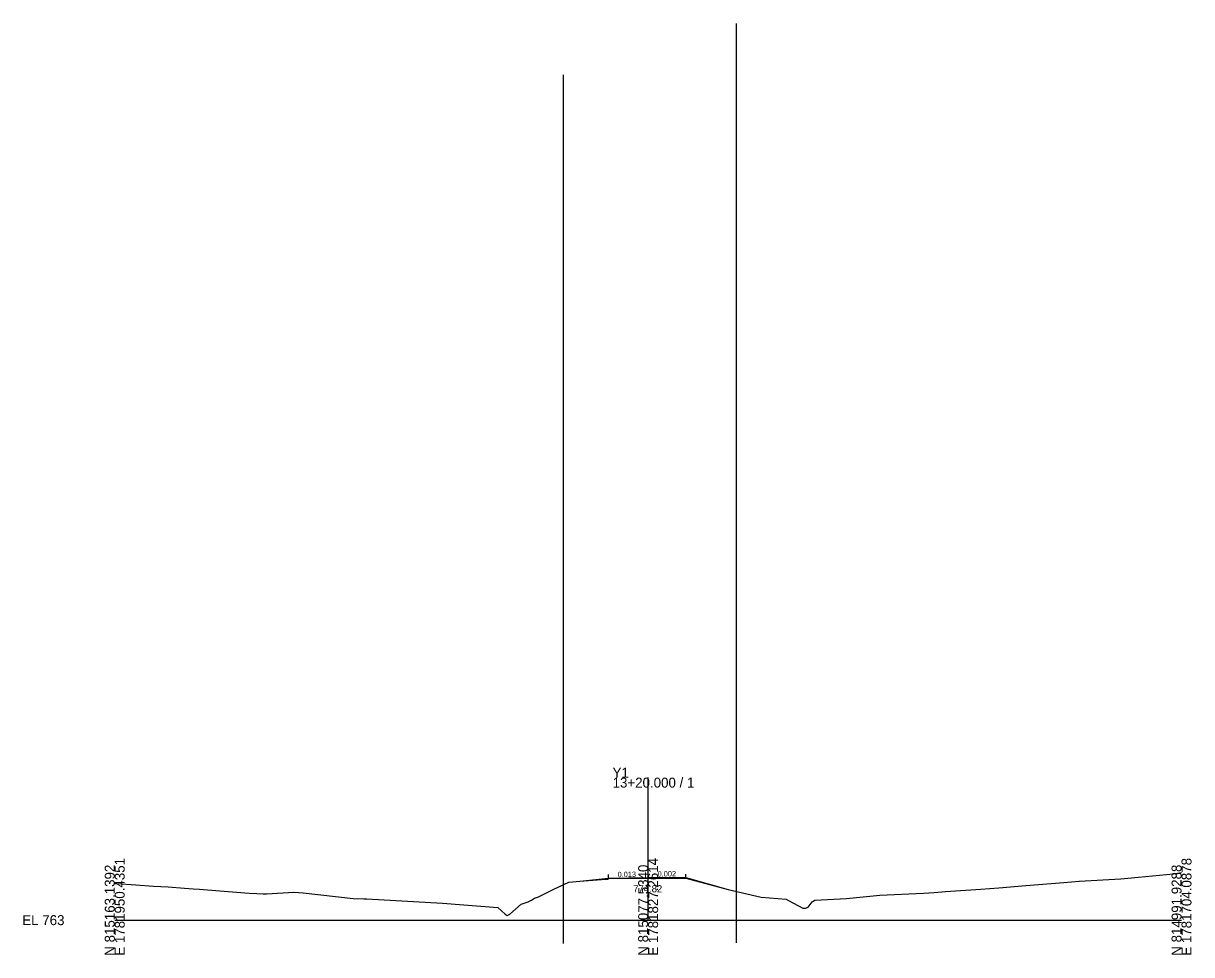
# Model space of a CAD drawing. Extents: x -26 to 3603, y -10 to 9847.
# Drawn here: x 3274.3 to 3602.8, y -9.7 to 252.1 of the extents above; entities that cross this region are included whole.
import ezdxf

# ---------------------------------------------------------------- set-up
doc = ezdxf.new("R2010")
doc.units = 0
for name, color, linetype in [('Exist Cross Section Cell', 7, 'Continuous'), ('Exist XS Center Line Elevation Label', 7, 'Continuous'), ('Exist XS Ground Line', 7, 'Continuous'), ('Prop XS EOT Tick Mark', 7, 'Continuous'), ('Prop XS Exc Vertical Line 1', 7, 'Continuous'), ('Prop XS Exc Vertical Line 2', 7, 'Continuous'), ('Prop XS Finish Grade Earthwork', 7, 'Continuous'), ('Prop XS Finish Grade Pavement', 7, 'Continuous'), ('Prop XS SE Text', 7, 'Continuous')]:
    doc.layers.add(name, color=color, linetype=linetype)

msp = doc.modelspace()

# ---------------------------------------------------------------- linework, layer by layer
at = {"layer": 'Exist Cross Section Cell'}
for p, q in [((3450, 0), (3450, 40.07)), ((3300, 0), (3450, 0)), ((3450, 0), (3600, 0))]:
    msp.add_line(p, q, dxfattribs=at)
at = {"layer": 'Exist XS Ground Line'}
for p, q in [((3597.73, 13.04), (3600, 13.36)), ((3300, 10.32), (3300.57, 10.3)), ((3300.57, 10.3), (3305.93, 9.91)), ((3305.93, 9.91), (3310.86, 9.58)), ((3423.52, 8.67), (3427.69, 10.69)), ((3427.69, 10.69), (3430.8, 10.94)), ((3430.8, 10.94), (3435.63, 11.38)), ((3435.63, 11.38), (3436.92, 11.46)), ((3436.92, 11.46), (3438.75, 11.51)), ((3438.75, 11.51), (3438.83, 11.69)), ((3438.83, 11.69), (3444.24, 11.76)), ((3444.24, 11.76), (3449.43, 11.82)), ((3449.43, 11.82), (3450, 11.82)), ((3450, 11.82), (3454.15, 11.82)), ((3454.15, 11.82), (3460.61, 11.84)), ((3460.61, 11.84), (3472.5, 8.65)), ((3556.21, 9.72), (3566.94, 10.63)), ((3566.94, 10.63), (3571.21, 10.97)), ((3571.21, 10.97), (3582.97, 11.66)), ((3582.97, 11.66), (3587.9, 12.04)), ((3587.9, 12.04), (3597.73, 13.04)), ((3310.86, 9.58), (3315, 9.33)), ((3315, 9.33), (3319.62, 8.97)), ((3319.62, 8.97), (3322.1, 8.8)), ((3322.1, 8.8), (3323.85, 8.73)), ((3323.85, 8.73), (3329.59, 8.25)), ((3329.59, 8.25), (3337.84, 7.63)), ((3337.84, 7.63), (3339.98, 7.51)), ((3339.98, 7.51), (3341.75, 7.41)), ((3341.75, 7.41), (3342.76, 7.36)), ((3342.76, 7.36), (3350.41, 7.84)), ((3350.41, 7.84), (3353.03, 7.72)), ((3353.03, 7.72), (3367.09, 6.11)), ((3419.17, 6.52), (3423.52, 8.67)), ((3472.5, 8.65), (3481.76, 6.47)), ((3505.77, 6.11), (3515.15, 6.99)), ((3515.15, 6.99), (3527.39, 7.63)), ((3527.39, 7.63), (3530.48, 7.81)), ((3530.48, 7.81), (3533.59, 8.04)), ((3533.59, 8.04), (3543.55, 8.75)), ((3543.55, 8.75), (3548.59, 9.12)), ((3548.59, 9.12), (3556.21, 9.72)), ((3367.09, 6.11), (3370.06, 6.01)), ((3370.06, 6.01), (3370.88, 5.99)), ((3370.88, 5.99), (3392.21, 4.76)), ((3392.21, 4.76), (3407.73, 3.54)), ((3407.73, 3.54), (3409.78, 1.66)), ((3411.14, 1.73), (3414.31, 4.47)), ((3414.31, 4.47), (3416.22, 5.15)), ((3416.22, 5.15), (3417.17, 5.66)), ((3417.17, 5.66), (3418.04, 6.15)), ((3418.04, 6.15), (3419.17, 6.52)), ((3481.76, 6.47), (3488.8, 5.89)), ((3488.8, 5.89), (3489.47, 5.48)), ((3489.47, 5.48), (3493.52, 3.4)), ((3493.52, 3.4), (3494.24, 3.41)), ((3494.24, 3.41), (3494.97, 3.66)), ((3494.97, 3.66), (3496.17, 5.12)), ((3496.17, 5.12), (3496.88, 5.62)), ((3496.88, 5.62), (3505.77, 6.11)), ((3409.78, 1.66), (3410.39, 1.34)), ((3410.39, 1.34), (3411.14, 1.73))]:
    msp.add_line(p, q, dxfattribs=at)
at = {"layer": 'Prop XS EOT Tick Mark'}
for p, q in [((3438.83, 11.82), (3438.83, 12.82)), ((3460.61, 11.96), (3460.61, 12.96))]:
    msp.add_line(p, q, dxfattribs=at)
at = {"layer": 'Prop XS Exc Vertical Line 1'}
msp.add_line((3426.22, -6.55), (3426.22, 237.69), dxfattribs=at)
at = {"layer": 'Prop XS Exc Vertical Line 2'}
msp.add_line((3474.83, -6.34), (3474.83, 252.14), dxfattribs=at)
at = {"layer": 'Prop XS Finish Grade Earthwork'}
for p, q in [((3430.8, 10.94), (3438.83, 11.82)), ((3460.61, 11.96), (3472.5, 8.65))]:
    msp.add_line(p, q, dxfattribs=at)
at = {"layer": 'Prop XS Finish Grade Pavement'}
for p, q in [((3438.83, 11.82), (3450, 11.96)), ((3450, 11.96), (3460.61, 11.96))]:
    msp.add_line(p, q, dxfattribs=at)

# ---------------------------------------------------------------- texts
at = {"layer": 'Exist Cross Section Cell'}
for s, p in [('Y1', (3440, 40.07)), ('13+20.000 / 1', (3440, 37.27)), ('EL 763', (3274, -1.4))]:
    msp.add_text(s, height=2.8, dxfattribs=at).set_placement(p)
for s, p in [('E 1781950.4351', (3302.8, -10)), ('E 1781827.2614', (3452.8, -10)), ('E 1781704.0878', (3602.8, -10)), ('N 815163.1392', (3300, -10)), ('N 815077.5340', (3450, -10)), ('N 814991.9288', (3600, -10))]:
    msp.add_text(s, height=2.8, rotation=90, dxfattribs=at).set_placement(p)
at = {"layer": 'Exist XS Center Line Elevation Label'}
msp.add_text('774.82', height=2, dxfattribs=at).set_placement((3445.79, 7.82))
at = {"layer": 'Prop XS SE Text'}
for s, rotation, p in [('0.013', 1.0885, (3441.42, 12.07)), ('0.002', 0.5075, (3452.67, 12.26))]:
    msp.add_text(s, height=1.5, rotation=rotation, dxfattribs=at).set_placement(p)

doc.saveas('drawing.dxf')
